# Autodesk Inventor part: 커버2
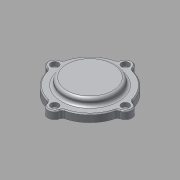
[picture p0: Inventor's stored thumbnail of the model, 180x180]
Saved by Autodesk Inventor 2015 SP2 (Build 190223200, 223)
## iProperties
Company: 한국ATC센터
Created: 2015-12
Part Number: 커버2
Document SubType Name: Modeling
Designer: mdu
Density: 2.71 g/cm^3
Material: 알루미늄 6061
Appearance: 알루미늄 - 평지
Author: mdu
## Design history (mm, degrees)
sketch "스케치1"
  geometry: C1 r 1.621 at (0, 6.75) reference; C2 r 1.621 at (-37, -30.25) reference; C3 r 1.621 at (0, -67.25) reference; C4 r 1.621 at (37, -30.25) reference; C5 r 10 at (0, -30.25) reference; C6 r 12 at (0, -30.25); C7 r 24.5 at (0, -30.25) reference; A1 r 3 centre (-38.77, -20.408) between (-38.239, -23.361) and (-35.862, -21.146) reference; A2 r 7 centre (-37, -30.25) between (-38.239, -23.361) and (-38.239, -37.139) reference; A3 r 3 centre (-38.77, -40.092) between (-35.862, -39.354) and (-38.239, -37.139) reference; A4 r 37 centre (0, -30.25) between (-35.862, -39.354) and (-9.104, -66.113) reference; A5 r 3 centre (-9.842, -69.02) between (-6.889, -68.489) and (-9.104, -66.113) reference; A6 r 7 centre (0, -67.25) between (-6.889, -68.489) and (6.889, -68.489) reference; A7 r 3 centre (9.842, -69.02) between (9.104, -66.112) and (6.889, -68.489) reference; A8 r 37 centre (0, -30.25) between (9.104, -66.112) and (35.863, -39.354) reference; A9 r 3 centre (38.77, -40.092) between (38.239, -37.139) and (35.863, -39.354) reference; A10 r 7 centre (37, -30.25) between (38.239, -37.139) and (38.239, -23.361) reference; A11 r 3 centre (38.77, -20.408) between (35.863, -21.146) and (38.239, -23.361) reference; A12 r 37 centre (0, -30.25) between (35.863, -21.146) and (9.104, 5.612) reference; A13 r 3 centre (9.842, 8.52) between (6.889, 7.989) and (9.104, 5.612) reference; A14 r 7 centre (0, 6.75) between (6.889, 7.989) and (-6.889, 7.989) reference; A15 r 3 centre (-9.842, 8.52) between (-9.104, 5.612) and (-6.889, 7.989) reference; A16 r 37 centre (0, -30.25) between (-9.104, 5.612) and (-35.862, -21.146) reference; 1 further point
  constraints: 1 centre point, 1 coincident
  dimensions: "d2" = 2 radial gap between concentric circles of C6 C5
extrude "돌출1" new body sketch "스케치1" distance "d0" = 8; taper "d1" = 0 deg
sketch "스케치2"
  geometry: C1 r 23.5 at (0, -30.25) reference; C2 r 12 at (0, -30.25) reference; 1 further point
extrude "돌출2" join sketch "스케치2" distance "d4" = 5; taper "d5" = 0 deg
sketch "스케치3"
  geometry: C1 r 23.5 at (0, 0) reference; C2 r 20.5 at (0, 0); 1 further point
  constraints: 1 centre point
  dimensions: "d6" = 3 radial gap between concentric circles of C2 C1
node "작업 평면1"
extrude "돌출3" join sketch "스케치3" stored distance "d7" = 5; taper "d8" = 0 deg
fillet "모깎기1" dims "d9" = 3
sketch "스케치4"
  geometry: C1 r 12 at (0, -30.25) reference; C2 r 27 at (0, -30.25); 1 further point
  constraints: 1 centre point
  dimensions: "d10" = 15 radial gap between concentric circles of C1 C2
extrude "돌출4" join sketch "스케치4" distance "d11" = 7; taper "d12" = 0 deg
fillet "모깎기2" dims "d13" = 3
chamfer "모따기1" distance "d14" = 1; stored, may be unused: second distance "d15" = 2, angle "d16" = 45 deg
node "작업점1"
  node "작업축1"
chamfer "모따기2" distance "d24" = 1; stored, may be unused: second distance "d25" = 2, angle "d26" = 45 deg
hole "구멍6" diameter "d43" = 4.5; stored, may be unused: countersink angle "d47" = 90 deg, drill point angle "d49" = 118 deg; dims "d41" = 10, "d42" = 10, "d44" = 6, "d45" = 8, "d46" = 4.4, "d48" = 8
fillet "모깎기4" dims "d60" = 3
node "솔리드1"
pattern_circular "원형 패턴1" dims angle "d51" = 360 deg
node "참조1"
node "참조2"
